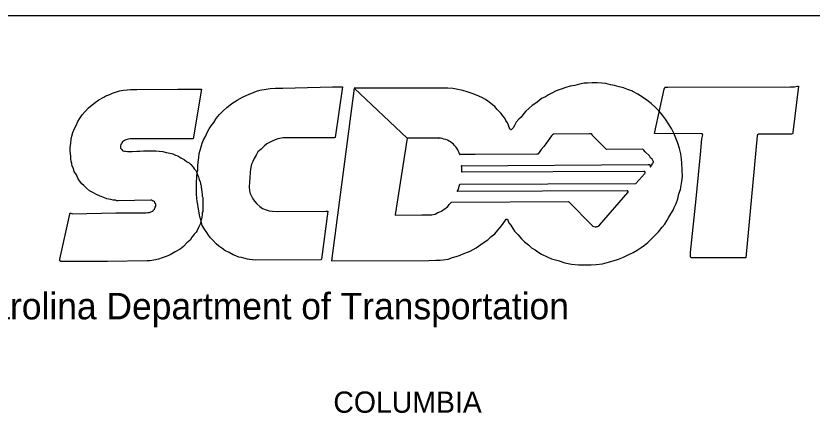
# Model space of a CAD drawing. Extents: x 190073 to 191750, y 195724 to 196797.
# Drawn here: x 190795.7 to 191020.5, y 196685 to 196797.1 of the extents above; entities that cross this region are included whole.
import ezdxf

# ---------------------------------------------------------------- set-up
doc = ezdxf.new("R2010")
doc.units = 0
doc.layers.add('RD_SHT_Bndy', color=7, linetype='Continuous')

# ---------------------------------------------------------------- blocks, each defined once
blk = doc.blocks.new('SCDOT')
for points in [[(0.0441557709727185, 0.026030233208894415), (0.044166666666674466, 0.026083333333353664), (0.04325000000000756, 0.026416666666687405), (0.04216666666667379, 0.026833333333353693), (0.041166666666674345, 0.027083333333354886), (0.0401666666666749, 0.027333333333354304), (0.03933333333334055, 0.027500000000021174), (0.0383333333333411, 0.02775000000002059), (0.0374166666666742, 0.027833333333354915), (0.03641666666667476, 0.027916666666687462), (0.03533333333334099, 0.027916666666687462), (0.03433333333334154, 0.027833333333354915), (0.033583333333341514, 0.027833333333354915), (0.03258333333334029, 0.027666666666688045), (0.031583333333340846, 0.027333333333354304), (0.0305833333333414, 0.027166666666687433), (0.029583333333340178, 0.026916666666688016), (0.028583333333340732, 0.026583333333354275), (0.027500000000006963, 0.026166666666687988), (0.026583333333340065, 0.025666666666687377), (0.025833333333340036, 0.025333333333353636), (0.02516666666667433, 0.024916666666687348), (0.024333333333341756, 0.02450000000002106), (0.02375000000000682, 0.02400000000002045), (0.023083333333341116, 0.023500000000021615), (0.022333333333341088, 0.023000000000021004), (0.021666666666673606, 0.022416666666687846), (0.020916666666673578, 0.021750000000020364), (0.02050000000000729, 0.02125000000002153), (0.019916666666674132, 0.0205000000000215), (0.01941666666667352, 0.02000000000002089), (0.018833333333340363, 0.019416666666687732), (0.0185000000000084, 0.018666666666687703), (0.018166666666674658, 0.018166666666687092), (0.017916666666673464, 0.01783333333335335), (0.01775000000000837, 0.017750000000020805), (0.017666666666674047, 0.017750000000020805), (0.0175833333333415, 0.017750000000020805), (0.01741666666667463, 0.018000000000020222), (0.017333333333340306, 0.018250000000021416), (0.017166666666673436, 0.01875000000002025), (0.01691666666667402, 0.01925000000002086), (0.016583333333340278, 0.019750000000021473), (0.01633333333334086, 0.020250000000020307), (0.01600000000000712, 0.02066666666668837), (0.015500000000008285, 0.021333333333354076), (0.01508333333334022, 0.021750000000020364), (0.014666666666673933, 0.022166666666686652), (0.014166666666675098, 0.022750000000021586), (0.013666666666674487, 0.023166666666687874), (0.0132500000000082, 0.023500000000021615), (0.012666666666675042, 0.023916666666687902), (0.01216666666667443, 0.02433333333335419), (0.011500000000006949, 0.02466666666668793), (0.01075000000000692, 0.02500000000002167), (0.009833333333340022, 0.02541666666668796), (0.00908333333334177, 0.025666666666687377), (0.008166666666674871, 0.026000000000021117), (0.007250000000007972, 0.026250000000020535), (0.006166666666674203, 0.02650000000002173), (0.005083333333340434, 0.026666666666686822), (0.004000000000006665, 0.026750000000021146), (0.0020833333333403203, 0.026750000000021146), (-0.01633333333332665, 0.026750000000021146), (-0.0048333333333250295, 0.015916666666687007), (-0.007416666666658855, -0.0007499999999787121), (-0.007416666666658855, -0.0008333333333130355), (-0.0016666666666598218, -0.0007499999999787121), (8.333333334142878e-05, -0.0007499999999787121), (0.0005000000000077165, -0.0007499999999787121), (0.0008333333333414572, -0.0006666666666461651), (0.001250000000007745, -0.0005833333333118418), (0.001833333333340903, -0.00024999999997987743), (0.0022500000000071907, -8.333333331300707e-05), (0.0025833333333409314, 8.333333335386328e-05), (0.003000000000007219, 0.000333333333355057), (0.00333333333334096, 0.0005833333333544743), (0.0036666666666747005, 0.0008333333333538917), (0.004000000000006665, 0.001083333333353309), (0.004250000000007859, 0.0015000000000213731), (0.004500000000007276, 0.0017500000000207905), (0.004750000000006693, 0.002000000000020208)], [(-0.08008333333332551, -0.010833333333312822), (-0.08024999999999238, -0.010749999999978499), (-0.08024999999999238, -0.010666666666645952), (-0.08024999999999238, -0.010499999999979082), (-0.08024999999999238, -0.010333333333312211), (-0.07966666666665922, -0.007749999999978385), (-0.07808333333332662, -0.0005833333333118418), (-0.07808333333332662, -0.0004999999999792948), (-0.0779999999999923, -0.00033333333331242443), (-0.07749999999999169, -0.0004999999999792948), (-0.06808333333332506, -0.00033333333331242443), (-0.06158333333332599, -0.00033333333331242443), (-0.0611666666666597, -0.00024999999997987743), (-0.060833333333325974, -0.00024999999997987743), (-0.06049999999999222, -8.333333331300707e-05), (-0.06008333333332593, 8.333333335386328e-05), (-0.05991666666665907, 0.000333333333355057), (-0.059749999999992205, 0.000500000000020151), (-0.05958333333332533, 0.0009166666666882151), (-0.05941666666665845, 0.0011666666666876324), (-0.05941666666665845, 0.0015000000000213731), (-0.05941666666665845, 0.0016666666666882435), (-0.05958333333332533, 0.0017500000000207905), (-0.059666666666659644, 0.0019166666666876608), (-0.059749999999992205, 0.002083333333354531), (-0.05991666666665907, 0.0022500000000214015), (-0.06016666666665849, 0.0023333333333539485), (-0.060333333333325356, 0.002416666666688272), (-0.06049999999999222, 0.002416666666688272), (-0.06758333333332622, 0.0023333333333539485), (-0.06791666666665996, 0.0023333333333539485), (-0.06816666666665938, 0.002416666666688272), (-0.06866666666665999, 0.002416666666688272), (-0.06916666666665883, 0.002583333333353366), (-0.07008333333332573, 0.0027500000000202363), (-0.07074999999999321, 0.00300000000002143), (-0.07149999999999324, 0.0033333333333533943), (-0.07233333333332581, 0.003666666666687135), (-0.07308333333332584, 0.004083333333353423), (-0.07383333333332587, 0.004500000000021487), (-0.07449999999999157, 0.005083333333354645), (-0.07508333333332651, 0.005666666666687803), (-0.0754999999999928, 0.006000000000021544), (-0.07599999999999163, 0.006666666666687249), (-0.07633333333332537, 0.007250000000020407), (-0.07666666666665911, 0.007916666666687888), (-0.07716666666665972, 0.008666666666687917), (-0.07733333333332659, 0.009333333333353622), (-0.07758333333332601, 0.009833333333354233), (-0.07766666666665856, 0.01041666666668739), (-0.07783333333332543, 0.010916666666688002), (-0.07791666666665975, 0.01133333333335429), (-0.07791666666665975, 0.011916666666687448), (-0.0779999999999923, 0.013166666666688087), (-0.0779999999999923, 0.013833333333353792), (-0.07791666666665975, 0.014833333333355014), (-0.07783333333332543, 0.01566666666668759), (-0.07766666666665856, 0.01633333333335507), (-0.07741666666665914, 0.017166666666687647), (-0.0770833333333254, 0.018000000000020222), (-0.07674999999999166, 0.018666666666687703), (-0.07633333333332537, 0.01950000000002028), (-0.07599999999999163, 0.020083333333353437), (-0.07541666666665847, 0.021000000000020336), (-0.07474999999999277, 0.021666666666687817), (-0.07408333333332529, 0.022500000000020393), (-0.07324999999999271, 0.023166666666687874), (-0.07258333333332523, 0.02366666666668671), (-0.0718333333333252, 0.024250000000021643), (-0.07074999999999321, 0.0248333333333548), (-0.0702499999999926, 0.02508333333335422), (-0.06941666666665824, 0.02541666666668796), (-0.06883333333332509, 0.025666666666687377), (-0.06816666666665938, 0.025916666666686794), (-0.06733333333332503, 0.026166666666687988), (-0.06641666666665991, 0.026333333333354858), (-0.06566666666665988, 0.026416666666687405), (-0.06491666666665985, 0.02650000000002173), (-0.06433333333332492, 0.02650000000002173), (-0.06358333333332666, 0.02650000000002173), (-0.05466666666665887, 0.026583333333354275), (-0.049499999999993, 0.026583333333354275), (-0.051333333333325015, 0.015750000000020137), (-0.0649999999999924, 0.015750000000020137), (-0.06541666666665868, 0.01566666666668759), (-0.0659166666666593, 0.015583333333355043), (-0.06624999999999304, 0.015416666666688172), (-0.06641666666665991, 0.015250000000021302), (-0.06666666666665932, 0.015083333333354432), (-0.0668333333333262, 0.014916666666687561), (-0.06691666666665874, 0.014750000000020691), (-0.06699999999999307, 0.014500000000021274), (-0.06708333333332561, 0.01425000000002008), (-0.06708333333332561, 0.014000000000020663), (-0.06708333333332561, 0.013750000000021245), (-0.06699999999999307, 0.013666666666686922), (-0.0668333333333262, 0.013416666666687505), (-0.06666666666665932, 0.013250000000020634), (-0.066583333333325, 0.013166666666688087), (-0.06624999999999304, 0.013083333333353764), (-0.06599999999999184, 0.013083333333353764), (-0.06558333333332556, 0.013000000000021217), (-0.06458333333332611, 0.013000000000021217), (-0.06358333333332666, 0.013083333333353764), (-0.06291666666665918, 0.013083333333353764), (-0.06208333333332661, 0.013166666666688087), (-0.05941666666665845, 0.013166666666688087), (-0.058666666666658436, 0.013083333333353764), (-0.057916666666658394, 0.013000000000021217), (-0.05716666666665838, 0.012833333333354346), (-0.056333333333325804, 0.012666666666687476), (-0.05574999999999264, 0.012500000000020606), (-0.055166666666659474, 0.012250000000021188), (-0.05466666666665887, 0.012083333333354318), (-0.05399999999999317, 0.01166666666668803), (-0.05324999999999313, 0.011250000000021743), (-0.052749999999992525, 0.010833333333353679), (-0.05216666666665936, 0.010583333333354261), (-0.05183333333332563, 0.010166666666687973), (-0.051333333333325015, 0.009583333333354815), (-0.05108333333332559, 0.009250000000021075), (-0.0506666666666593, 0.008833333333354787), (-0.05058333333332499, 0.008583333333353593), (-0.05041666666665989, 0.008166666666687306), (-0.050333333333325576, 0.007833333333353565), (-0.0501666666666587, 0.0075000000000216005), (-0.05008333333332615, 0.007250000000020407), (-0.04999999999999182, 0.006916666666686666), (-0.04983333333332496, 0.006416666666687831), (-0.04974999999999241, 0.006166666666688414), (-0.04974999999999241, 0.006000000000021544), (-0.049666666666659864, 0.00575000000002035), (-0.049583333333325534, 0.005500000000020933), (-0.049583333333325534, 0.005333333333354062), (-0.049583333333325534, 0.005166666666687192), (-0.049499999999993, 0.0050000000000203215), (-0.049499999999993, 0.004666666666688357), (-0.04941666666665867, 0.0043333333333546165), (-0.04941666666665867, 0.004083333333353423), (-0.049333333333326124, 0.0038333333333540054), (-0.049333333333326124, 0.003583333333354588), (-0.049333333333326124, 0.0033333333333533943), (-0.04924999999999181, 0.00300000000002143), (-0.04924999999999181, 0.0027500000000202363), (-0.04924999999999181, 0.0023333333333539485), (-0.04924999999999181, 0.002083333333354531), (-0.04924999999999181, 0.0017500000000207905), (-0.04924999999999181, 0.0014166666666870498), (-0.04924999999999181, 0.001083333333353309), (-0.04924999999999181, 0.0009166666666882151), (-0.04924999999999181, 0.0008333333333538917), (-0.04924999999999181, 0.0005833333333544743), (-0.04924999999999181, 0.00025000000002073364), (-0.04924999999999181, 2.1316282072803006e-14), (-0.049333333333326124, -0.00024999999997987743), (-0.049333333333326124, -0.0005833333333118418), (-0.049333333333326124, -0.0008333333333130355), (-0.04941666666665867, -0.0010833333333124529), (-0.04941666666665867, -0.0013333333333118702), (-0.049499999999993, -0.001583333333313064), (-0.049583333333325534, -0.0018333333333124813), (-0.049666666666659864, -0.0020833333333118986), (-0.049666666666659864, -0.0023333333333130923), (-0.04974999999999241, -0.0024999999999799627), (-0.04983333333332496, -0.00274999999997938), (-0.04999999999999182, -0.0031666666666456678), (-0.0501666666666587, -0.0034999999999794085), (-0.05041666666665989, -0.0041666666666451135), (-0.0506666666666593, -0.004499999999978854), (-0.05108333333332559, -0.004916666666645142), (-0.05124999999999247, -0.005166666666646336), (-0.05158333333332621, -0.005583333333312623), (-0.0519999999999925, -0.0062499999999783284), (-0.05266666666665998, -0.006833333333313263), (-0.05341666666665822, -0.007583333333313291), (-0.054166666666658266, -0.00816666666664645), (-0.055249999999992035, -0.008749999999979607), (-0.056333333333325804, -0.009416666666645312), (-0.05716666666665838, -0.009749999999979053), (-0.05808333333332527, -0.010083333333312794), (-0.0588333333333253, -0.010333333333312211), (-0.05983333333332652, -0.010583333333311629), (-0.060749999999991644, -0.010749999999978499), (-0.06133333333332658, -0.010749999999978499), (-0.06991666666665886, -0.010833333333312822), (-0.08008333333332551, -0.010833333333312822)], [(-0.03783333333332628, -0.010583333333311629), (-0.03841666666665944, -0.010499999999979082), (-0.03908333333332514, -0.010416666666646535), (-0.03949999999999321, -0.010333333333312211), (-0.04033333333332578, -0.010166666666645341), (-0.040833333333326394, -0.00999999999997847), (-0.04141666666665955, -0.009916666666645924), (-0.04208333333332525, -0.009666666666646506), (-0.042666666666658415, -0.009416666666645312), (-0.043499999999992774, -0.008916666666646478), (-0.044416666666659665, -0.008499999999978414), (-0.045083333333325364, -0.007999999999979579), (-0.045749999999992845, -0.007499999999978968), (-0.04633333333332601, -0.006999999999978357), (-0.04699999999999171, -0.006333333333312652), (-0.047583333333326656, -0.005749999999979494), (-0.047999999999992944, -0.005166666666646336), (-0.0483333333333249, -0.004583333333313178), (-0.04883333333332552, -0.003833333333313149), (-0.049333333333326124, -0.0030833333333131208), (-0.04941666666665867, -0.0026666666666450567), (-0.049583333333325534, -0.0020833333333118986), (-0.04983333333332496, -0.0014166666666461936), (-0.04991666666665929, -0.0008333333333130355), (-0.04999999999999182, -0.00033333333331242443), (-0.05008333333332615, 0.00016666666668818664), (-0.050249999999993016, 0.0009166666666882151), (-0.050333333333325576, 0.0015000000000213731), (-0.05041666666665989, 0.002166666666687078), (-0.05049999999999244, 0.0029166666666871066), (-0.05058333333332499, 0.0037500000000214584), (-0.05058333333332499, 0.004166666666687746), (-0.05058333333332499, 0.004666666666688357), (-0.05058333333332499, 0.0049166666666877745), (-0.05058333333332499, 0.005333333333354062), (-0.05058333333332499, 0.00575000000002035), (-0.05058333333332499, 0.006166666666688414), (-0.05058333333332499, 0.006750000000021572), (-0.05049999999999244, 0.007083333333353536), (-0.05049999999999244, 0.007416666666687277), (-0.05049999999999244, 0.007833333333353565), (-0.05041666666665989, 0.008166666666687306), (-0.05041666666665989, 0.008500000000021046), (-0.050333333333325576, 0.008833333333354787), (-0.050333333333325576, 0.009083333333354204), (-0.050333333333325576, 0.00991666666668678), (-0.050249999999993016, 0.010666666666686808), (-0.05008333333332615, 0.011750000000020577), (-0.04999999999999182, 0.012583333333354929), (-0.04983333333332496, 0.013333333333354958), (-0.049583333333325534, 0.014000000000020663), (-0.049333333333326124, 0.014833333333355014), (-0.04908333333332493, 0.015583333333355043), (-0.048583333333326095, 0.016416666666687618), (-0.048249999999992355, 0.017166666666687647), (-0.04783333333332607, 0.017916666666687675), (-0.04741666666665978, 0.01858333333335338), (-0.046833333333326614, 0.01933333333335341), (-0.04633333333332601, 0.02016666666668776), (-0.04558333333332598, 0.02108333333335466), (-0.04483333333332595, 0.021833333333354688), (-0.043999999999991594, 0.022583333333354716), (-0.043333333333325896, 0.02308333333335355), (-0.04291666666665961, 0.02341666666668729), (-0.04174999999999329, 0.02416666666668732), (-0.0405833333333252, 0.0248333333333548), (-0.03949999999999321, 0.025333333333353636), (-0.03858333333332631, 0.025666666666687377), (-0.037583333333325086, 0.026083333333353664), (-0.03683333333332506, 0.026333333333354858), (-0.035916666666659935, 0.02650000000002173), (-0.03458333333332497, 0.026666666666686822), (-0.033416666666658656, 0.026750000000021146), (-0.03183333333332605, 0.026750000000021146), (-0.02916666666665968, 0.026833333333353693), (-0.021083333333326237, 0.027083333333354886), (-0.0189166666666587, 0.027083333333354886), (-0.02049999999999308, 0.016083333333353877), (-0.02066666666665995, 0.01600000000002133), (-0.030833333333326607, 0.01600000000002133), (-0.03174999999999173, 0.01600000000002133), (-0.03249999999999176, 0.01583333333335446), (-0.03291666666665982, 0.015750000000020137), (-0.03349999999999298, 0.015583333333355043), (-0.034333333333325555, 0.015166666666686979), (-0.035333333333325, 0.014666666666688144), (-0.035916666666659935, 0.014166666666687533), (-0.03658333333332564, 0.013500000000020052), (-0.03724999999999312, 0.012916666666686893), (-0.03766666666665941, 0.012250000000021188), (-0.0380833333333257, 0.01150000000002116), (-0.038333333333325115, 0.010833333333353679), (-0.038666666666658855, 0.01025000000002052), (-0.038833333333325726, 0.009166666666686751), (-0.03891666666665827, 0.008500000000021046), (-0.038999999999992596, 0.007250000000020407), (-0.03908333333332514, 0.006333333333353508), (-0.039166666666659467, 0.005333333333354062), (-0.03908333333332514, 0.004500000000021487), (-0.03891666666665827, 0.003916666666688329), (-0.038666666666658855, 0.0033333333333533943), (-0.038333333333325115, 0.0027500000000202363), (-0.03799999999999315, 0.0022500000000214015), (-0.03749999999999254, 0.0016666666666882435), (-0.03683333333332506, 0.001083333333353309), (-0.0362499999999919, 0.0006666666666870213), (-0.03549999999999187, 0.000333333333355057), (-0.034833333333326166, 0.00016666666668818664), (-0.03408333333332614, 8.333333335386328e-05), (-0.033083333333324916, 2.1316282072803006e-14), (-0.02249999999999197, 8.333333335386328e-05), (-0.022083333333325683, 8.333333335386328e-05), (-0.02341666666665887, -0.010333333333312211), (-0.023499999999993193, -0.010416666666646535), (-0.02358333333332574, -0.010499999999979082), (-0.03783333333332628, -0.010583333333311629)], [(0.0019755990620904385, 0.01591026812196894), (0.0020000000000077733, 0.015916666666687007), (-0.0048333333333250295, 0.015916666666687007), (-0.01633333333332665, 0.026750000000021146), (-0.021249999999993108, -0.010749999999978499), (-0.00016666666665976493, -0.010666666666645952), (0.0014166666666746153, -0.010583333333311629), (0.002333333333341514, -0.010583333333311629), (0.003000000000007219, -0.010499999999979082), (0.004083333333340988, -0.010333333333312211), (0.005000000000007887, -0.00999999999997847), (0.0063333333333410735, -0.009666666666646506), (0.00766666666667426, -0.009083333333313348), (0.008833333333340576, -0.008583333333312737), (0.010166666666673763, -0.007916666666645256), (0.01166666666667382, -0.006833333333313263), (0.012666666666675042, -0.0061666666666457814), (0.013333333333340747, -0.0054999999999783), (0.014166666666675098, -0.004833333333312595), (0.014833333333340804, -0.0040833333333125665), (0.015333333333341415, -0.0034999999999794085), (0.01583333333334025, -0.002833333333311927), (0.01633333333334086, -0.0020833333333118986), (0.0166666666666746, -0.001666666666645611), (0.01691666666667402, -0.001666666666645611), (0.01708333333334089, -0.0020833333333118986), (0.01725000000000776, -0.0024999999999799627), (0.017666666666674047, -0.0029999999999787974), (0.018083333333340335, -0.003666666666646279), (0.0185000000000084, -0.004249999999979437), (0.019166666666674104, -0.004999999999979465), (0.02000000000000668, -0.005916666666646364), (0.02066666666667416, -0.006583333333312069), (0.021500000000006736, -0.007249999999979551), (0.022166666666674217, -0.007916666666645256), (0.022916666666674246, -0.00833333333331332), (0.023500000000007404, -0.008749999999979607), (0.024333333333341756, -0.009249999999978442), (0.02558333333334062, -0.0098333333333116), (0.026500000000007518, -0.010249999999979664), (0.027916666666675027, -0.010666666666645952), (0.029416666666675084, -0.011166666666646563), (0.030833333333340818, -0.01141666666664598), (0.032333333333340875, -0.01158333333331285), (0.03366666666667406, -0.01158333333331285), (0.03508333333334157, -0.01158333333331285), (0.036166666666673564, -0.011499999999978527), (0.037583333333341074, -0.011333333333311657), (0.03858333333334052, -0.01108333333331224), (0.039916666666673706, -0.010749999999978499), (0.04108333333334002, -0.010333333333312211), (0.04216666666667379, -0.009916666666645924), (0.04316666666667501, -0.009416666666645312), (0.044250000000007, -0.008916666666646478), (0.04508333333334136, -0.008416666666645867), (0.04600000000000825, -0.007833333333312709), (0.04666666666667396, -0.007333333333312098), (0.04741666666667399, -0.0067499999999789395), (0.048000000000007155, -0.0061666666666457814), (0.048583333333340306, -0.005583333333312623), (0.04925000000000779, -0.004916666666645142), (0.049750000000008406, -0.004416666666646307), (0.05050000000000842, -0.003416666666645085), (0.051083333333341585, -0.00274999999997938), (0.05158333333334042, -0.0019166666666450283), (0.05200000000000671, -0.0012499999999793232), (0.052416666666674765, -0.0004999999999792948), (0.05291666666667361, 0.00025000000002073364), (0.05316666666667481, 0.0008333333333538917), (0.053583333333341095, 0.0017500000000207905), (0.05391666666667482, 0.0027500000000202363), (0.054166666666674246, 0.0038333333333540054), (0.054500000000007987, 0.004750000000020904), (0.054666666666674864, 0.005666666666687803), (0.05483333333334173, 0.006500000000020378), (0.054916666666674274, 0.0075833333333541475), (0.05483333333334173, 0.010500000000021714), (0.0547500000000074, 0.01133333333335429), (0.054754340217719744, 0.011344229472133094)], [(0.056916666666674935, -0.010083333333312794), (0.05675000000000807, -0.00999999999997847), (0.05666666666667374, -0.009749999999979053), (0.05666666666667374, -0.008916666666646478), (0.05791666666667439, 0.0027500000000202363), (0.058666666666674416, 0.010166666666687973), (0.05875000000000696, 0.011583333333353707), (0.05891666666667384, 0.013166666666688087), (0.05900000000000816, 0.014083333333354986), (0.059166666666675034, 0.015750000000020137), (0.05933333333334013, 0.016666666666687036), (0.05925000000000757, 0.016833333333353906), (0.059083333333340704, 0.016833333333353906), (0.0488333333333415, 0.01691666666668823), (0.05008333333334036, 0.022583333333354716), (0.05100000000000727, 0.026583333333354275), (0.051083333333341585, 0.026916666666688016), (0.05116666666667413, 0.027000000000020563), (0.05125000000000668, 0.027000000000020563), (0.05175000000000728, 0.027000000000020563), (0.07833333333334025, 0.027083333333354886), (0.07925000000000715, 0.027083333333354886), (0.07991666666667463, 0.027166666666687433), (0.08000000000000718, 0.027166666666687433), (0.08016666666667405, 0.027166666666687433), (0.07891666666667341, 0.017166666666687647), (0.07891666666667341, 0.01691666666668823), (0.07883333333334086, 0.016833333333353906), (0.07858333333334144, 0.01675000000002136), (0.0714166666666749, 0.01675000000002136), (0.07125000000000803, 0.016666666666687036), (0.0711666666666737, 0.016416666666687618), (0.0686666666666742, -0.010083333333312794), (0.056916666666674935, -0.010083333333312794)], [(0.00698664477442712, 0.00991462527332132), (0.006916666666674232, 0.00991666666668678), (0.047500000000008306, 0.010166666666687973), (0.04783333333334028, 0.010166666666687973), (0.04783333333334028, 0.010000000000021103), (0.047916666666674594, 0.010000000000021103), (0.047916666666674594, 0.00991666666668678), (0.047916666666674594, 0.009750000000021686), (0.048000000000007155, 0.009666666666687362), (0.04808333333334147, 0.009666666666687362), (0.04808333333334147, 0.009750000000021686), (0.04816666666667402, 0.009833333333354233), (0.04825000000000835, 0.010000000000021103), (0.04841666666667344, 0.010333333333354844), (0.04850000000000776, 0.010500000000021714), (0.048583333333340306, 0.010583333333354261), (0.048666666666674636, 0.010750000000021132), (0.048666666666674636, 0.010833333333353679), (0.048583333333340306, 0.010916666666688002), (0.04850000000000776, 0.011083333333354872), (0.04833333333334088, 0.01133333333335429), (0.048000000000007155, 0.01166666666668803), (0.04775000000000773, 0.012083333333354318), (0.046833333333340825, 0.012916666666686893), (0.046583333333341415, 0.013333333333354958), (0.04641666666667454, 0.013416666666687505), (0.046250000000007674, 0.013500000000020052), (0.03841666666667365, 0.013416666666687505), (0.03533333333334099, 0.01658333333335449), (0.03525000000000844, 0.01675000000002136), (0.03525000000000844, 0.016833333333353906), (0.03516666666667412, 0.01691666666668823), (0.03508333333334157, 0.016833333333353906), (0.03475000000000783, 0.016833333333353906), (0.027083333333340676, 0.01675000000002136), (0.026916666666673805, 0.01675000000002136), (0.026750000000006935, 0.016666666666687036), (0.026666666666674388, 0.01658333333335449), (0.026500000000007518, 0.016416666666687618), (0.026166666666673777, 0.015916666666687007), (0.02575000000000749, 0.015416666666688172), (0.025250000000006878, 0.014666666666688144), (0.02483333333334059, 0.014083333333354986), (0.024250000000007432, 0.013416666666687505), (0.023833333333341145, 0.012833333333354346), (0.023500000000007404, 0.012416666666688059), (0.023333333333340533, 0.012416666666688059), (0.009916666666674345, 0.012333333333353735), (0.006500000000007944, 0.012333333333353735), (0.006559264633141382, 0.012333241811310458)], [(0.006593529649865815, 0.0058957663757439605), (0.006583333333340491, 0.00591666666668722), (0.044833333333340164, 0.006083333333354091), (0.04675000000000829, 0.008250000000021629), (0.046833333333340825, 0.008416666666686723), (0.046833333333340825, 0.008500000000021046), (0.046833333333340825, 0.008583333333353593), (0.04675000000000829, 0.008583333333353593), (0.04675000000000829, 0.008666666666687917), (0.04666666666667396, 0.008666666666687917), (0.046583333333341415, 0.008666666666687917), (0.007083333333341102, 0.008500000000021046), (0.007004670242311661, 0.008494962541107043)], [(0.004750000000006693, 0.002000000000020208), (0.030166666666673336, 0.002166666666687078), (0.03533333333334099, -0.0030833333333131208), (0.03550000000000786, -0.0031666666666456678), (0.03566666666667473, -0.003249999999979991), (0.03600000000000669, -0.003333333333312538), (0.036166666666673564, -0.003333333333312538), (0.036333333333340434, -0.003249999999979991), (0.03658333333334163, -0.003249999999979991), (0.036666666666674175, -0.0031666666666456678), (0.03691666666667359, -0.0029999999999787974), (0.0430833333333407, 0.004083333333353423), (0.04313134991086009, 0.004121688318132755)], [(0.0429657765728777, 0.004484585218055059), (0.043000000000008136, 0.004500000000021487), (0.006083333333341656, 0.0043333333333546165), (0.006037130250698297, 0.004309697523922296)]]:
    blk.add_lwpolyline(points)
for centre, radius, start, end in [((0.035592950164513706, 0.008683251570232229), 0.019345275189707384, 7.9062055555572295, 63.7281222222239), ((0.0017531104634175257, 0.0106799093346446), 0.005235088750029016, 52.83069722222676, 87.56422500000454), ((0.0017579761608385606, 0.010995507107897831), 0.0049841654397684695, 15.568897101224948, 50.68284432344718), ((-0.0049457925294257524, 0.009053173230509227), 0.011963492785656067, 357.325636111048, 4.129255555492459), ((-0.0050338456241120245, 0.009084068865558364), 0.01205658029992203, 336.6718222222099, 344.6660222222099), ((0.042966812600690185, 0.004265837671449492), 0.0002187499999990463, 318.77874999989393, 90.27136111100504)]:
    blk.add_arc(centre, radius, start, end)
blk.add_text('South Carolina Department of Transportation', height=0.00575).set_placement((-0.12314743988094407, -0.023416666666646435))

msp = doc.modelspace()

# ---------------------------------------------------------------- linework, layer by layer
at = {"layer": 'RD_SHT_Bndy'}
msp.add_line((191747.5577192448, 196797.11522228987), (190072.5577192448, 196797.11522228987), dxfattribs=at)

# ---------------------------------------------------------------- block references
at = {"xscale": 1300, "yscale": 1300}
msp.add_blockref('SCDOT', (190912.44188591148, 196741.9360556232), dxfattribs=at)

# ---------------------------------------------------------------- texts
msp.add_text('COLUMBIA', height=6).set_placement((190885.3018859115, 196685.12722228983))

doc.saveas('drawing.dxf')
